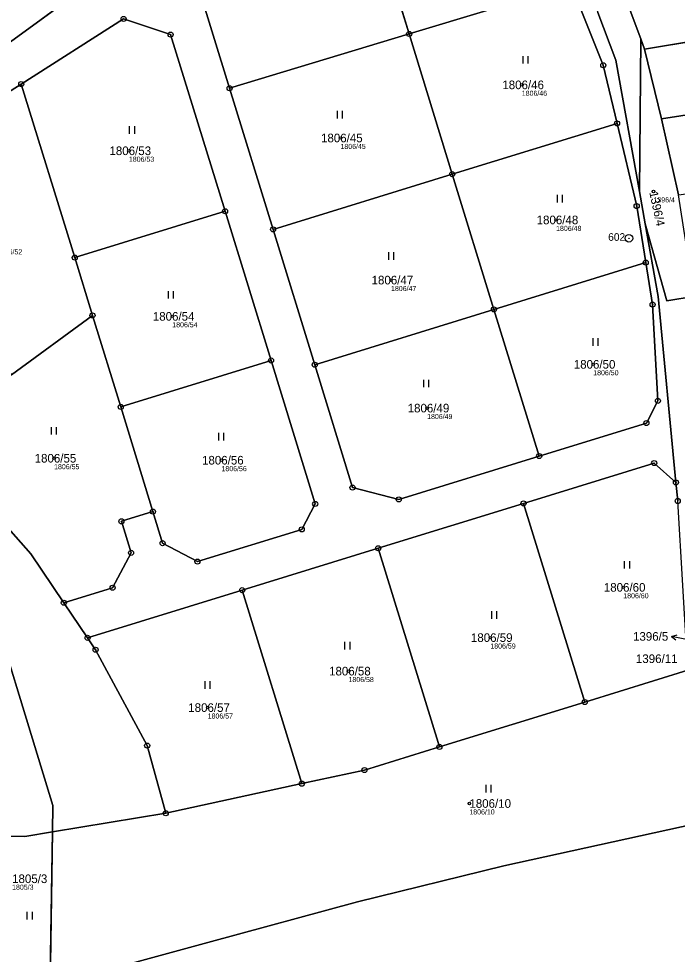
# Model space of a CAD drawing. Extents: x -762274 to -759271, y -1061928 to -1059060.
# Drawn here: x -760701.7 to -760571.8, y -1060553.3 to -1060368.9 of the extents above; entities that cross this region are included whole.
import ezdxf

# ---------------------------------------------------------------- set-up
doc = ezdxf.new("R2010")
doc.units = 0
for name, color, linetype in [('Definiční body', 7, 'Continuous'), ('Hranice parcel', 7, 'Continuous'), ('Parcelní čísla', 7, 'Continuous'), ('Polygon parcely', 7, 'Continuous'), ('Pop  PČ popisy', 7, 'Continuous'), ('Značky bodu BP', 7, 'Continuous'), ('Značky kultur', 7, 'Continuous')]:
    doc.layers.add(name, color=color, linetype=linetype)

msp = doc.modelspace()

# ---------------------------------------------------------------- linework, layer by layer
at = {"layer": 'Definiční body'}
for centre in [(-760602.44, -1060381.9), (-760638.22, -1060392.38), (-760679.97, -1060394.9), (-760576.45, -1060402.92), (-760595.67, -1060408.54), (-760628.24, -1060420.4), (-760671.41, -1060427.55), (-760588.34, -1060437.01), (-760621.12, -1060445.64), (-760694.73, -1060455.53), (-760661.7, -1060455.92), (-760582.41, -1060480.99), (-760608.64, -1060490.9), (-760636.63, -1060497.51), (-760664.42, -1060504.7), (-760612.78, -1060523.61)]:
    msp.add_circle(centre, 0.25, dxfattribs=at)
at = {"layer": 'Hranice parcel'}
for p, q in [((-760624.67, -1060371.86), (-760636.2, -1060334.47)), ((-760585, -1060356.64), (-760578.96, -1060372.84)), ((-760624.67, -1060371.86), (-760592.69, -1060362.18)), ((-760690.78, -1060364.23), (-760711.33, -1060379.23)), ((-760578.2, -1060374.89), (-760550.5, -1060370.25)), ((-760660.09, -1060382.58), (-760624.67, -1060371.86)), ((-760616.15, -1060399.51), (-760624.67, -1060371.86)), ((-760579.24, -1060402.95), (-760578.96, -1060372.84)), ((-760578.96, -1060372.84), (-760578.2, -1060374.89)), ((-760578.2, -1060374.89), (-760574.87, -1060388.58)), ((-760690.66, -1060415.97), (-760701.21, -1060381.75)), ((-760651.51, -1060410.41), (-760660.09, -1060382.58)), ((-760574.87, -1060388.58), (-760546.43, -1060384.17)), ((-760616.15, -1060399.51), (-760583.65, -1060389.49)), ((-760574.87, -1060388.58), (-760571.52, -1060403.58)), ((-760651.51, -1060410.41), (-760616.15, -1060399.51)), ((-760607.93, -1060426.18), (-760616.15, -1060399.51)), ((-760579.24, -1060402.95), (-760578.1, -1060409.28)), ((-760690.66, -1060415.97), (-760660.99, -1060406.82)), ((-760660.99, -1060406.82), (-760651.91, -1060436.25)), ((-760643.29, -1060437.08), (-760651.51, -1060410.41)), ((-760687.15, -1060427.37), (-760690.66, -1060415.97)), ((-760607.93, -1060426.18), (-760577.97, -1060416.95)), ((-760643.29, -1060437.08), (-760607.93, -1060426.18)), ((-760599.01, -1060455.11), (-760607.93, -1060426.18)), ((-760703.15, -1060439.09), (-760687.15, -1060427.37)), ((-760687.15, -1060427.37), (-760681.59, -1060445.4)), ((-760681.59, -1060445.4), (-760651.91, -1060436.25)), ((-760675.23, -1060466.05), (-760681.59, -1060445.4)), ((-760602.1, -1060464.43), (-760576.32, -1060456.49)), ((-760576.32, -1060456.49), (-760572.02, -1060460.29)), ((-760572.02, -1060460.29), (-760571.67, -1060463.96)), ((-760630.77, -1060473.27), (-760602.1, -1060464.43)), ((-760590.02, -1060503.62), (-760602.1, -1060464.43)), ((-760657.6, -1060481.54), (-760630.77, -1060473.27)), ((-760618.69, -1060512.45), (-760630.77, -1060473.27)), ((-760688.12, -1060490.95), (-760657.6, -1060481.54)), ((-760645.84, -1060519.7), (-760657.6, -1060481.54)), ((-760688.12, -1060490.95), (-760692.81, -1060484.02)), ((-760569.66, -1060497.34), (-760590.02, -1060503.62)), ((-760590.02, -1060503.62), (-760618.69, -1060512.45)), ((-760645.84, -1060519.7), (-760672.7, -1060525.53)), ((-760695.06, -1060529.2), (-760672.7, -1060525.53)), ((-760695.53, -1060559.49), (-760695.06, -1060529.2))]:
    msp.add_line(p, q, dxfattribs=at)
for points in [[(-760615.07, -1060309.26), (-760590.71, -1060358.77), (-760587.41, -1060367.62), (-760583.91, -1060377.02), (-760579.24, -1060402.95)], [(-760660.09, -1060382.58), (-760666.31, -1060362.47), (-760656.27, -1060351.89), (-760660.16, -1060344.9)], [(-760592.69, -1060362.18), (-760586.37, -1060378.04), (-760583.65, -1060389.49)], [(-760701.21, -1060381.75), (-760681.01, -1060368.91), (-760671.75, -1060371.99), (-760660.99, -1060406.82)], [(-760729.23, -1060406), (-760704.46, -1060383.81), (-760701.21, -1060381.75)], [(-760583.65, -1060389.49), (-760579.77, -1060405.79), (-760577.97, -1060416.95)], [(-760568.25, -1060423.54), (-760573.83, -1060424.52), (-760578.1, -1060409.28)], [(-760578.1, -1060409.28), (-760575.51, -1060423.66), (-760572.02, -1060460.29)], [(-760577.97, -1060416.95), (-760576.63, -1060425.23), (-760575.58, -1060444.21), (-760577.86, -1060448.59), (-760599.01, -1060455.11)], [(-760651.91, -1060436.25), (-760643.21, -1060464.55), (-760645.86, -1060469.55), (-760666.46, -1060475.9), (-760673.33, -1060472.27), (-760675.23, -1060466.05)], [(-760599.01, -1060455.11), (-760626.72, -1060463.65), (-760635.84, -1060461.31), (-760643.29, -1060437.08)], [(-760692.81, -1060484.02), (-760699.34, -1060474.36), (-760714.11, -1060457.67), (-760720.53, -1060451.82)], [(-760675.23, -1060466.05), (-760681.46, -1060467.97), (-760679.54, -1060474.18), (-760683.18, -1060481.06), (-760692.81, -1060484.02)], [(-760695.06, -1060529.2), (-760694.98, -1060524), (-760710.01, -1060475.1), (-760729.15, -1060470.28), (-760732.82, -1060469.35)], [(-760672.7, -1060525.53), (-760676.37, -1060512.2), (-760686.54, -1060493.29), (-760688.12, -1060490.95)], [(-760618.69, -1060512.45), (-760633.5, -1060517.02), (-760645.84, -1060519.7)], [(-760568.21, -1060527.61), (-760605.95, -1060535.93), (-760634.83, -1060543.03), (-760664.41, -1060551.01), (-760695.53, -1060559.49)], [(-760706.7, -1060530.04), (-760700.51, -1060530.09), (-760695.06, -1060529.2)]]:
    msp.add_lwpolyline(points, dxfattribs=at)
at = {"layer": 'Polygon parcely'}
for points in [[(-760619.13, -1060291.1), (-760615.07, -1060309.26), (-760590.71, -1060358.77), (-760587.41, -1060367.62), (-760583.91, -1060377.02), (-760579.24, -1060402.95), (-760578.96, -1060372.84), (-760585, -1060356.64)], [(-760624.67, -1060371.86), (-760592.69, -1060362.18), (-760596.93, -1060351.54), (-760609.88, -1060324.86), (-760636.2, -1060334.47)], [(-760711.31, -1060336.11), (-760733.07, -1060352), (-760733.24, -1060352.16), (-760711.33, -1060379.23), (-760690.78, -1060364.23)], [(-760624.67, -1060371.86), (-760636.2, -1060334.47), (-760640.22, -1060335.94), (-760660.16, -1060344.9), (-760656.27, -1060351.89), (-760666.31, -1060362.47), (-760660.09, -1060382.58)], [(-760578.96, -1060372.84), (-760578.2, -1060374.89), (-760550.5, -1060370.25), (-760552.95, -1060360.23), (-760555.48, -1060360.68), (-760559.27, -1060353.57), (-760560.42, -1060350.57), (-760585, -1060356.64)], [(-760583.65, -1060389.49), (-760586.37, -1060378.04), (-760592.69, -1060362.18), (-760624.67, -1060371.86), (-760616.15, -1060399.51)], [(-760660.99, -1060406.82), (-760671.75, -1060371.99), (-760681.01, -1060368.91), (-760701.21, -1060381.75), (-760690.66, -1060415.97)], [(-760574.87, -1060388.58), (-760546.43, -1060384.17), (-760548.79, -1060375.55), (-760550.5, -1060370.25), (-760578.2, -1060374.89)], [(-760616.15, -1060399.51), (-760624.67, -1060371.86), (-760660.09, -1060382.58), (-760651.51, -1060410.41)], [(-760579.24, -1060402.95), (-760578.1, -1060409.28), (-760573.83, -1060424.52), (-760568.25, -1060423.54), (-760568.41, -1060422.52), (-760569.69, -1060415.45), (-760571.52, -1060403.58), (-760574.87, -1060388.58), (-760578.2, -1060374.89), (-760578.96, -1060372.84)], [(-760703.15, -1060439.09), (-760687.15, -1060427.37), (-760690.66, -1060415.97), (-760701.21, -1060381.75), (-760704.46, -1060383.81), (-760729.23, -1060406)], [(-760541.93, -1060399.73), (-760544.24, -1060391.16), (-760546.43, -1060384.17), (-760574.87, -1060388.58), (-760571.52, -1060403.58)], [(-760577.97, -1060416.95), (-760579.77, -1060405.79), (-760583.65, -1060389.49), (-760616.15, -1060399.51), (-760607.93, -1060426.18)], [(-760692.81, -1060484.02), (-760699.34, -1060474.36), (-760714.11, -1060457.67), (-760720.53, -1060451.82), (-760750.22, -1060424.8), (-760777.06, -1060400.36), (-760782.99, -1060414.08), (-760732.82, -1060469.35), (-760729.15, -1060470.28), (-760710.01, -1060475.1), (-760694.98, -1060524), (-760695.06, -1060529.2), (-760672.7, -1060525.53), (-760676.37, -1060512.2), (-760686.54, -1060493.29), (-760688.12, -1060490.95)], [(-760607.93, -1060426.18), (-760616.15, -1060399.51), (-760651.51, -1060410.41), (-760643.29, -1060437.08)], [(-760651.91, -1060436.25), (-760660.99, -1060406.82), (-760690.66, -1060415.97), (-760687.15, -1060427.37), (-760681.59, -1060445.4)], [(-760599.01, -1060455.11), (-760577.86, -1060448.59), (-760575.58, -1060444.21), (-760576.63, -1060425.23), (-760577.97, -1060416.95), (-760607.93, -1060426.18)], [(-760599.01, -1060455.11), (-760607.93, -1060426.18), (-760643.29, -1060437.08), (-760635.84, -1060461.31), (-760626.72, -1060463.65)], [(-760681.59, -1060445.4), (-760687.15, -1060427.37), (-760703.15, -1060439.09), (-760720.53, -1060451.82), (-760714.11, -1060457.67), (-760699.34, -1060474.36), (-760692.81, -1060484.02), (-760683.18, -1060481.06), (-760679.54, -1060474.18), (-760681.46, -1060467.97), (-760675.23, -1060466.05)], [(-760675.23, -1060466.05), (-760673.33, -1060472.27), (-760666.46, -1060475.9), (-760645.86, -1060469.55), (-760643.21, -1060464.55), (-760651.91, -1060436.25), (-760681.59, -1060445.4)], [(-760571.67, -1060463.96), (-760572.02, -1060460.29), (-760576.32, -1060456.49), (-760602.1, -1060464.43), (-760590.02, -1060503.62), (-760569.66, -1060497.34)], [(-760590.02, -1060503.62), (-760602.1, -1060464.43), (-760630.77, -1060473.27), (-760618.69, -1060512.45)], [(-760729.15, -1060470.28), (-760732.82, -1060469.35), (-760720.92, -1060482.47), (-760713.82, -1060504.89), (-760712.97, -1060507.56), (-760706.98, -1060527.78), (-760706.7, -1060530.04), (-760700.51, -1060530.09), (-760695.06, -1060529.2), (-760694.98, -1060524), (-760710.01, -1060475.1)], [(-760618.69, -1060512.45), (-760630.77, -1060473.27), (-760657.6, -1060481.54), (-760645.84, -1060519.7), (-760633.5, -1060517.02)], [(-760645.84, -1060519.7), (-760657.6, -1060481.54), (-760688.12, -1060490.95), (-760686.54, -1060493.29), (-760676.37, -1060512.2), (-760672.7, -1060525.53)], [(-760590.02, -1060503.62), (-760618.69, -1060512.45), (-760633.5, -1060517.02), (-760645.84, -1060519.7), (-760672.7, -1060525.53), (-760695.06, -1060529.2), (-760695.53, -1060559.49), (-760664.41, -1060551.01), (-760634.83, -1060543.03), (-760605.95, -1060535.93), (-760568.21, -1060527.61), (-760569.66, -1060497.34)], [(-760548.02, -1060525.68), (-760556.35, -1060507.49), (-760557.1, -1060525.03), (-760562.1, -1060526.14), (-760568.21, -1060527.61), (-760605.95, -1060535.93), (-760634.83, -1060543.03), (-760664.41, -1060551.01), (-760695.53, -1060559.49), (-760695.82, -1060578.7), (-760685.63, -1060605.22), (-760673.38, -1060620.04), (-760624.88, -1060614.17), (-760609.96, -1060635.44), (-760605.09, -1060635.69), (-760579.51, -1060626.59), (-760560.37, -1060620.2), (-760541.38, -1060607.59), (-760514.67, -1060589.81), (-760533.86, -1060562.2)], [(-760695.06, -1060529.2), (-760700.51, -1060530.09), (-760706.7, -1060530.04), (-760703.23, -1060557.66), (-760695.53, -1060559.49)]]:
    msp.add_lwpolyline(points, close=True, dxfattribs=at)
for points in [[(-760592.69, -1060362.18), (-760586.37, -1060378.04), (-760583.65, -1060389.49), (-760579.77, -1060405.79), (-760577.97, -1060416.95), (-760576.63, -1060425.23), (-760575.58, -1060444.21), (-760577.86, -1060448.59), (-760599.01, -1060455.11), (-760626.72, -1060463.65), (-760635.84, -1060461.31), (-760643.29, -1060437.08), (-760651.51, -1060410.41), (-760660.09, -1060382.58), (-760666.31, -1060362.47)], [(-760690.78, -1060364.23), (-760711.33, -1060379.23)], [(-760704.46, -1060383.81), (-760701.21, -1060381.75), (-760681.01, -1060368.91), (-760671.75, -1060371.99), (-760660.99, -1060406.82), (-760651.91, -1060436.25), (-760643.21, -1060464.55), (-760645.86, -1060469.55), (-760666.46, -1060475.9), (-760673.33, -1060472.27), (-760675.23, -1060466.05), (-760681.46, -1060467.97), (-760679.54, -1060474.18), (-760683.18, -1060481.06), (-760692.81, -1060484.02), (-760688.12, -1060490.95), (-760657.6, -1060481.54), (-760630.77, -1060473.27), (-760602.1, -1060464.43), (-760576.32, -1060456.49), (-760572.02, -1060460.29), (-760575.51, -1060423.66), (-760578.1, -1060409.28), (-760579.24, -1060402.95), (-760583.91, -1060377.02), (-760587.41, -1060367.62)], [(-760568.25, -1060423.54), (-760573.83, -1060424.52), (-760578.1, -1060409.28), (-760575.51, -1060423.66), (-760572.02, -1060460.29), (-760571.67, -1060463.96)]]:
    msp.add_lwpolyline(points, dxfattribs=at)
at = {"layer": 'Pop  PČ popisy'}
for p, q in [((-760572.89, -1060490.66), (-760571.8, -1060490.37)), ((-760569.95, -1060491.28), (-760572.89, -1060490.66)), ((-760572.89, -1060490.66), (-760572.01, -1060491.35))]:
    msp.add_line(p, q, dxfattribs=at)
at = {"layer": 'Značky bodu BP'}
for centre, radius in [((-760681.01, -1060368.91), 0.5), ((-760681.01, -1060368.91), 0.0303), ((-760671.75, -1060371.99), 0.5), ((-760671.75, -1060371.99), 0.0303), ((-760624.67, -1060371.86), 0.5), ((-760624.67, -1060371.86), 0.0303), ((-760586.37, -1060378.04), 0.5), ((-760586.37, -1060378.04), 0.0303), ((-760701.21, -1060381.75), 0.5), ((-760701.21, -1060381.75), 0.0303), ((-760660.09, -1060382.58), 0.5), ((-760660.09, -1060382.58), 0.0303), ((-760583.65, -1060389.49), 0.5), ((-760583.65, -1060389.49), 0.0303), ((-760616.15, -1060399.51), 0.5), ((-760616.15, -1060399.51), 0.0303), ((-760660.99, -1060406.82), 0.5), ((-760579.77, -1060405.79), 0.5), ((-760579.77, -1060405.79), 0.0303), ((-760660.99, -1060406.82), 0.0303), ((-760651.51, -1060410.41), 0.5), ((-760651.51, -1060410.41), 0.0303), ((-760581.29, -1060412.15), 0.75), ((-760581.29, -1060412.15), 0.03), ((-760690.66, -1060415.97), 0.5), ((-760690.66, -1060415.97), 0.0303), ((-760577.97, -1060416.95), 0.5), ((-760577.97, -1060416.95), 0.0303), ((-760576.63, -1060425.23), 0.5), ((-760607.93, -1060426.18), 0.5), ((-760607.93, -1060426.18), 0.0303), ((-760576.63, -1060425.23), 0.0303), ((-760687.15, -1060427.37), 0.5), ((-760687.15, -1060427.37), 0.0303), ((-760651.91, -1060436.25), 0.5), ((-760651.91, -1060436.25), 0.0303), ((-760643.29, -1060437.08), 0.5), ((-760643.29, -1060437.08), 0.0303), ((-760681.59, -1060445.4), 0.5), ((-760575.58, -1060444.21), 0.5), ((-760575.58, -1060444.21), 0.0303), ((-760681.59, -1060445.4), 0.0303), ((-760577.86, -1060448.59), 0.5), ((-760577.86, -1060448.59), 0.0303), ((-760599.01, -1060455.11), 0.5), ((-760599.01, -1060455.11), 0.0303), ((-760576.32, -1060456.49), 0.5), ((-760576.32, -1060456.49), 0.0303), ((-760572.02, -1060460.29), 0.5), ((-760635.84, -1060461.31), 0.5), ((-760635.84, -1060461.31), 0.0303), ((-760572.02, -1060460.29), 0.0303), ((-760626.72, -1060463.65), 0.5), ((-760571.67, -1060463.96), 0.5), ((-760643.21, -1060464.55), 0.5), ((-760643.21, -1060464.55), 0.0303), ((-760626.72, -1060463.65), 0.0303), ((-760602.1, -1060464.43), 0.5), ((-760602.1, -1060464.43), 0.0303), ((-760675.23, -1060466.05), 0.5), ((-760675.23, -1060466.05), 0.0303), ((-760681.46, -1060467.97), 0.5), ((-760681.46, -1060467.97), 0.0303), ((-760645.86, -1060469.55), 0.5), ((-760645.86, -1060469.55), 0.0303), ((-760673.33, -1060472.27), 0.5), ((-760673.33, -1060472.27), 0.0303), ((-760630.77, -1060473.27), 0.5), ((-760679.54, -1060474.18), 0.5), ((-760679.54, -1060474.18), 0.0303), ((-760630.77, -1060473.27), 0.0303), ((-760666.46, -1060475.9), 0.5), ((-760666.46, -1060475.9), 0.0303), ((-760683.18, -1060481.06), 0.5), ((-760683.18, -1060481.06), 0.0303), ((-760657.6, -1060481.54), 0.5), ((-760657.6, -1060481.54), 0.0303), ((-760692.81, -1060484.02), 0.5), ((-760692.81, -1060484.02), 0.0303), ((-760688.12, -1060490.95), 0.5), ((-760688.12, -1060490.95), 0.0303), ((-760686.54, -1060493.29), 0.5), ((-760686.54, -1060493.29), 0.0303), ((-760590.02, -1060503.62), 0.5), ((-760590.02, -1060503.62), 0.0303), ((-760676.37, -1060512.2), 0.5), ((-760676.37, -1060512.2), 0.0303), ((-760618.69, -1060512.45), 0.5), ((-760618.69, -1060512.45), 0.0303), ((-760633.5, -1060517.02), 0.5), ((-760633.5, -1060517.02), 0.0303), ((-760645.84, -1060519.7), 0.5), ((-760645.84, -1060519.7), 0.0303), ((-760672.7, -1060525.53), 0.5), ((-760672.7, -1060525.53), 0.0303)]:
    msp.add_circle(centre, radius, dxfattribs=at)
at = {"layer": 'Značky kultur'}
for p, q in [((-760602.18, -1060377.71), (-760602.18, -1060376.21)), ((-760601.18, -1060377.71), (-760601.18, -1060376.21)), ((-760638.83, -1060388.54), (-760638.83, -1060387.04)), ((-760637.83, -1060388.54), (-760637.83, -1060387.04)), ((-760679.82, -1060391.56), (-760679.82, -1060390.06)), ((-760678.82, -1060391.56), (-760678.82, -1060390.06)), ((-760595.38, -1060405.1), (-760595.38, -1060403.6)), ((-760594.38, -1060405.1), (-760594.38, -1060403.6)), ((-760628.67, -1060416.41), (-760628.67, -1060414.91)), ((-760627.67, -1060416.41), (-760627.67, -1060414.91)), ((-760672.14, -1060424.06), (-760672.14, -1060422.56)), ((-760671.14, -1060424.06), (-760671.14, -1060422.56)), ((-760588.36, -1060433.38), (-760588.36, -1060431.88)), ((-760587.36, -1060433.38), (-760587.36, -1060431.88)), ((-760621.79, -1060441.54), (-760621.79, -1060440.04)), ((-760620.79, -1060441.54), (-760620.79, -1060440.04)), ((-760695.24, -1060450.87), (-760695.24, -1060449.37)), ((-760694.24, -1060450.87), (-760694.24, -1060449.37)), ((-760662.21, -1060452.04), (-760662.21, -1060450.54)), ((-760661.21, -1060452.04), (-760661.21, -1060450.54)), ((-760582.14, -1060477.3), (-760582.14, -1060475.8)), ((-760581.14, -1060477.3), (-760581.14, -1060475.8)), ((-760608.38, -1060487.21), (-760608.38, -1060485.71)), ((-760607.38, -1060487.21), (-760607.38, -1060485.71)), ((-760637.33, -1060493.24), (-760637.33, -1060491.74)), ((-760636.33, -1060493.24), (-760636.33, -1060491.74)), ((-760664.93, -1060501.01), (-760664.93, -1060499.51)), ((-760663.93, -1060501.01), (-760663.93, -1060499.51)), ((-760609.49, -1060521.41), (-760609.49, -1060519.91)), ((-760608.49, -1060521.41), (-760608.49, -1060519.91)), ((-760700.02, -1060546.48), (-760700.02, -1060544.98)), ((-760699.02, -1060546.48), (-760699.02, -1060544.98))]:
    msp.add_line(p, q, dxfattribs=at)

# ---------------------------------------------------------------- texts
at = {"layer": 'Definiční body'}
for s, p in [('1806/46', (-760602.44, -1060384.06)), ('1806/45', (-760638.22, -1060394.54)), ('1806/53', (-760679.97, -1060397.06)), ('1396/4', (-760576.45, -1060405.08)), ('1806/48', (-760595.67, -1060410.7)), ('1806/52', (-760706.01, -1060415.33)), ('1806/47', (-760628.24, -1060422.56)), ('1806/54', (-760671.41, -1060429.71)), ('1806/50', (-760588.34, -1060439.17)), ('1806/49', (-760621.12, -1060447.8)), ('1806/55', (-760694.73, -1060457.69)), ('1806/56', (-760661.7, -1060458.08)), ('1806/60', (-760582.41, -1060483.15)), ('1806/59', (-760608.64, -1060493.06)), ('1806/58', (-760636.63, -1060499.67)), ('1806/57', (-760664.42, -1060506.86)), ('1806/10', (-760612.78, -1060525.77)), ('1805/3', (-760703.02, -1060540.61))]:
    msp.add_text(s, height=1, dxfattribs=at).set_placement(p)
at = {"layer": 'Parcelní čísla'}
for s, p in [('1806/46', (-760606.28, -1060382.75)), ('1806/45', (-760642.06, -1060393.23)), ('1806/53', (-760683.81, -1060395.75)), ('1806/48', (-760599.51, -1060409.39)), ('1806/47', (-760632.08, -1060421.25)), ('1806/54', (-760675.25, -1060428.4)), ('1806/50', (-760592.18, -1060437.86)), ('1806/49', (-760624.96, -1060446.49)), ('1806/55', (-760698.57, -1060456.38)), ('1806/56', (-760665.54, -1060456.77)), ('1806/60', (-760586.25, -1060481.84)), ('1806/59', (-760612.48, -1060491.75)), ('1396/5', (-760580.49, -1060491.51)), ('1396/11', (-760579.92, -1060495.91)), ('1806/58', (-760640.47, -1060498.36)), ('1806/57', (-760668.26, -1060505.55)), ('1806/10', (-760612.78, -1060524.46)), ('1805/3', (-760703.02, -1060539.3))]:
    msp.add_text(s, height=1.7, dxfattribs=at).set_placement(p)
msp.add_text('1396/4', height=1.7, rotation=282, dxfattribs=at).set_placement((-760577.28, -1060403.1))
at = {"layer": 'Značky bodu BP'}
msp.add_text('602', height=1.5, dxfattribs=at).set_placement((-760585.39, -1060412.65))

doc.saveas('drawing.dxf')
